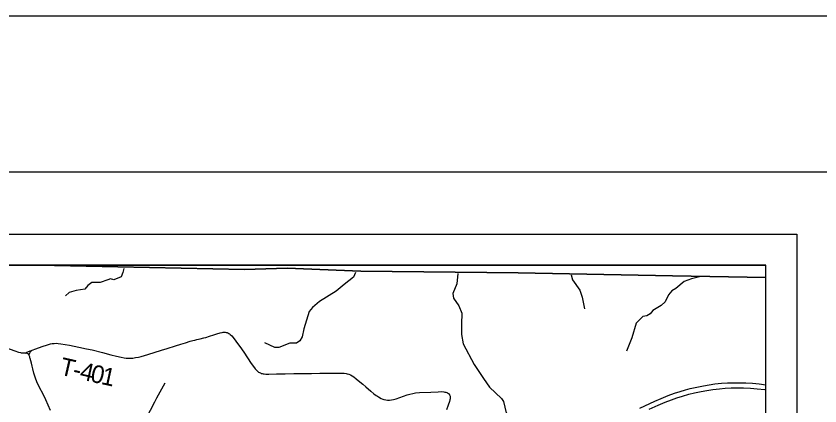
# Model space of a CAD drawing. Extents: x 0 to 34, y 0 to 22.
# Drawn here: x 6.991 to 9.575, y 20.748 to 22 of the extents above; entities that cross this region are included whole.
import ezdxf

# ---------------------------------------------------------------- set-up
doc = ezdxf.new("R2010")
doc.units = 0
for name, color, linetype in [('GM_X_Adjacent_County', 7, 'Continuous'), ('GM_X_County', 7, 'Continuous'), ('GM_X_Minor_River', 7, 'Continuous'), ('GM_X_State_Route', 7, 'Continuous'), ('GM_X_Township', 7, 'Continuous'), ('GM_X_Township_Road', 7, 'Continuous'), ('GM_X_Township_Road_Text', 7, 'Continuous'), ('SH_Border', 7, 'Continuous'), ('SH_Cut_Line', 7, 'Continuous'), ('SH_Data', 7, 'Continuous')]:
    doc.layers.add(name, color=color, linetype=linetype)

msp = doc.modelspace()

# ---------------------------------------------------------------- linework, layer by layer
at = {"layer": 'GM_X_Adjacent_County'}
for points in [[(9.4013, 21.1598), (9.4013, 21.2003), (7.0736, 21.2003)], [(7.0736, 21.2003), (7.1148, 21.1984), (7.7257, 21.186), (7.8629, 21.1903), (8.099, 21.1805), (8.605, 21.1754), (9.1005, 21.1651), (9.4013, 21.1598)]]:
    msp.add_lwpolyline(points, dxfattribs=at)
at = {"layer": 'GM_X_County'}
for points in [[(7.0736, 21.2003), (2.6013, 21.2003), (2.6013, 14.4003), (9.4013, 14.4003), (9.4013, 21.1598)], [(9.4013, 21.1598), (9.1005, 21.1651), (8.605, 21.1754), (8.099, 21.1805), (7.8629, 21.1903), (7.7257, 21.186), (7.1148, 21.1984), (7.0736, 21.2003)]]:
    msp.add_lwpolyline(points, dxfattribs=at)
at = {"layer": 'GM_X_Minor_River'}
for points in [[(7.3376, 21.1892), (7.3341, 21.1764), (7.3289, 21.1626), (7.3055, 21.1523), (7.2944, 21.1563), (7.2866, 21.1522), (7.2612, 21.1442), (7.2347, 21.1445), (7.2215, 21.1346), (7.2129, 21.1228), (7.1845, 21.1181), (7.1622, 21.1124), (7.1498, 21.1017)], [(8.0827, 21.1766), (8.0762, 21.1611), (8.0456, 21.1375), (8.0203, 21.1166), (7.9663, 21.083), (7.9444, 21.0639), (7.9331, 21.0514), (7.9167, 20.9952), (7.9108, 20.9694), (7.9036, 20.9572), (7.8927, 20.9496), (7.8715, 20.9495), (7.836, 20.9353), (7.8231, 20.9357), (7.7913, 20.9507)], [(8.4113, 21.1729), (8.4074, 21.1403), (8.3955, 21.1084), (8.397, 21.0936), (8.4138, 21.0694), (8.4237, 21.046), (8.4228, 21.0099), (8.4233, 20.9773), (8.4287, 20.9473), (8.4631, 20.8811), (8.4939, 20.8353), (8.5133, 20.8077), (8.5517, 20.7718), (8.5578, 20.7616), (8.5663, 20.7255), (8.5842, 20.6949), (8.5964, 20.6828)], [(8.7758, 21.169), (8.7791, 21.1532), (8.8035, 21.1198), (8.8111, 21.0967), (8.8181, 21.0599)], [(9.1924, 21.163), (9.1618, 21.1563), (9.1384, 21.1471), (9.112, 21.125), (9.0984, 21.1178), (9.0882, 21.1045), (9.0773, 21.0824), (9.0641, 21.0702), (9.0381, 21.0538), (9.0294, 21.0439), (9.0185, 21.0375), (9.006, 21.0348), (8.9837, 21.0131), (8.9707, 20.9667), (8.9527, 20.9234)], [(7.41, 20.7073), (7.4374, 20.7605), (7.4442, 20.7738), (7.4708, 20.8217)]]:
    msp.add_lwpolyline(points, dxfattribs=at)
at = {"layer": 'GM_X_State_Route'}
for points in [[(8.9964, 20.7408), (9.0442, 20.7633), (9.064, 20.772), (9.0871, 20.7811), (9.1075, 20.7886), (9.1252, 20.7943), (9.143, 20.7995), (9.158, 20.8034), (9.1792, 20.8083), (9.2004, 20.8127), (9.2188, 20.8157), (9.2372, 20.8182), (9.2588, 20.8203), (9.2774, 20.8216), (9.296, 20.8222), (9.3146, 20.8223), (9.3363, 20.8217), (9.3579, 20.8204), (9.3795, 20.8184), (9.4013, 20.8158)], [(9.0263, 20.7369), (9.0545, 20.7498), (9.0774, 20.7596), (9.0976, 20.7676), (9.1152, 20.7739), (9.133, 20.7795), (9.1539, 20.7854), (9.172, 20.7899), (9.1933, 20.7944), (9.2117, 20.7977), (9.2302, 20.8003), (9.2518, 20.8028), (9.2704, 20.8043), (9.289, 20.8053), (9.3077, 20.8057), (9.3294, 20.8054), (9.3512, 20.8044), (9.3728, 20.8026), (9.3976, 20.8), (9.4013, 20.7995)]]:
    msp.add_lwpolyline(points, dxfattribs=at)
at = {"layer": 'GM_X_Township'}
for p, q in [((7.0736, 21.2003), (6.2234, 21.2003)), ((9.4013, 16.1226), (9.4013, 21.1598))]:
    msp.add_line(p, q, dxfattribs=at)
msp.add_lwpolyline([(9.4013, 21.1598), (9.1005, 21.1651), (8.605, 21.1754), (8.099, 21.1805), (7.8629, 21.1903), (7.7257, 21.186), (7.1148, 21.1984), (7.0736, 21.2003)], dxfattribs=at)
at = {"layer": 'GM_X_Township_Road'}
for points in [[(7.021, 20.9175), (7.0206, 20.9175), (7.0123, 20.917), (7.0092, 20.9172), (7.0062, 20.9178), (7.0002, 20.9194), (6.9885, 20.9235), (6.9359, 20.9421), (6.9241, 20.946), (6.9065, 20.9521), (6.8862, 20.9599), (6.8661, 20.9679), (6.8459, 20.976), (6.8371, 20.979), (6.8311, 20.9806), (6.8281, 20.9811), (6.8219, 20.9815), (6.8188, 20.9815), (6.8126, 20.9808), (6.8065, 20.9797), (6.7974, 20.9777), (6.7734, 20.9715), (6.683, 20.95)], [(7.0415, 20.9257), (7.0431, 20.9264), (7.0545, 20.9312), (7.0751, 20.9383), (7.0928, 20.9441), (7.1018, 20.9466), (7.1079, 20.9478), (7.114, 20.9486), (7.1202, 20.9488), (7.1264, 20.9486), (7.1357, 20.9474), (7.1631, 20.9423), (7.1936, 20.9362), (7.2179, 20.9314), (7.2361, 20.9273), (7.2692, 20.9192), (7.2963, 20.912), (7.3143, 20.9073), (7.3294, 20.9038), (7.3385, 20.9022), (7.3447, 20.9014), (7.3509, 20.9009), (7.3571, 20.9009), (7.3664, 20.9015), (7.3756, 20.9028), (7.3847, 20.9046), (7.3937, 20.9069), (7.4145, 20.9132), (7.459, 20.9268), (7.4768, 20.9323), (7.5036, 20.9403), (7.5213, 20.9459), (7.5361, 20.9506), (7.5509, 20.9554), (7.5598, 20.9579), (7.5658, 20.9594), (7.5718, 20.9608), (7.5835, 20.9634), (7.595, 20.9663), (7.6009, 20.9679), (7.6126, 20.9717), (7.6274, 20.9763), (7.6362, 20.979), (7.6477, 20.9824), (7.6538, 20.9837), (7.6574, 20.9842), (7.6601, 20.9844), (7.6634, 20.9843), (7.6664, 20.984), (7.6694, 20.9831), (7.6722, 20.982), (7.675, 20.9807), (7.6775, 20.979), (7.6799, 20.9771), (7.6843, 20.9727), (7.6922, 20.9632), (7.6979, 20.9559), (7.7035, 20.9485), (7.7108, 20.9384), (7.7229, 20.9204), (7.7349, 20.9023), (7.7469, 20.8843), (7.7541, 20.8742), (7.7598, 20.8668), (7.7639, 20.8622), (7.7661, 20.8601), (7.7685, 20.8582), (7.7709, 20.8564), (7.7736, 20.8548), (7.7764, 20.8534), (7.7792, 20.8523), (7.7822, 20.8514), (7.7852, 20.8508), (7.7883, 20.8504), (7.7945, 20.8501), (7.8038, 20.85), (7.8286, 20.8504), (7.8565, 20.851), (7.8845, 20.8513), (7.9062, 20.8516), (7.9248, 20.8519), (7.9403, 20.8521), (7.9681, 20.8525), (7.9836, 20.8525), (8.0053, 20.8526), (8.0395, 20.8527), (8.0457, 20.8524), (8.0519, 20.8516), (8.0549, 20.8511), (8.0609, 20.8494), (8.0666, 20.847), (8.072, 20.8441), (8.0772, 20.8407), (8.0845, 20.8351), (8.0964, 20.8253), (8.1057, 20.8171), (8.115, 20.8089), (8.1315, 20.7947), (8.1412, 20.787), (8.1487, 20.7815), (8.1531, 20.7787)], [(7.021, 20.9175), (7.0228, 20.9187), (7.0245, 20.9195), (7.0259, 20.9201), (7.0341, 20.9235), (7.0365, 20.9242), (7.039, 20.9249), (7.0415, 20.9257)], [(7.0334, 20.9108), (7.0337, 20.913), (7.0339, 20.9144), (7.0342, 20.9155), (7.0354, 20.9184), (7.0365, 20.9201), (7.0383, 20.9226), (7.0395, 20.9239), (7.0403, 20.9246), (7.0415, 20.9257)], [(7.0334, 20.9108), (7.0327, 20.9119), (7.0315, 20.9134), (7.0303, 20.9145), (7.0288, 20.9155), (7.0275, 20.9163), (7.0255, 20.917), (7.0235, 20.9175), (7.021, 20.9175)], [(7.1018, 20.7331), (7.0943, 20.7501), (7.0869, 20.7672), (7.0803, 20.7812), (7.0647, 20.8114), (7.0586, 20.825), (7.0536, 20.8371), (7.0518, 20.8428), (7.0486, 20.8525), (7.0453, 20.8665), (7.0431, 20.8755), (7.041, 20.8845), (7.037, 20.8995), (7.0361, 20.9026), (7.0354, 20.9051), (7.0348, 20.9072), (7.0339, 20.9097), (7.0334, 20.9108)], [(8.1531, 20.7787), (8.1565, 20.7765), (8.1647, 20.7719), (8.1704, 20.7695), (8.1733, 20.7685), (8.1793, 20.7671), (8.1855, 20.7664), (8.1917, 20.7663), (8.1979, 20.7669), (8.204, 20.7679), (8.213, 20.7703), (8.2248, 20.7742), (8.2481, 20.7829), (8.257, 20.7857), (8.266, 20.7879), (8.2752, 20.7894), (8.2876, 20.7904), (8.3248, 20.792), (8.3478, 20.793), (8.3576, 20.7935), (8.3658, 20.7929), (8.3697, 20.7923), (8.3727, 20.7916), (8.3755, 20.7905), (8.3782, 20.7895), (8.3806, 20.7879), (8.3828, 20.786), (8.3845, 20.7837), (8.3858, 20.7809), (8.3863, 20.7791), (8.3865, 20.7772), (8.3867, 20.7736), (8.3864, 20.7707), (8.3855, 20.7669), (8.384, 20.7614), (8.38, 20.7496), (8.3749, 20.7349)]]:
    msp.add_lwpolyline(points, dxfattribs=at)
at = {"layer": 'SH_Border'}
msp.add_lwpolyline([(2, 21.5), (33.5, 21.5), (33.5, 0.5), (2, 0.5)], close=True, dxfattribs=at)
at = {"layer": 'SH_Cut_Line'}
msp.add_lwpolyline([(0, 0), (34, 0), (34, 22), (0, 22)], close=True, dxfattribs=at)
at = {"layer": 'SH_Data'}
for p, q in [((2.5, 21.2997), (9.5, 21.2997)), ((9.5, 21.2997), (9.5, 14.2997)), ((2.6, 21.1997), (9.4, 21.1997)), ((9.4, 21.1997), (9.4, 14.3997))]:
    msp.add_line(p, q, dxfattribs=at)

# ---------------------------------------------------------------- texts
at = {"layer": 'GM_X_Township_Road_Text'}
for s, rotation, p in [('T', 347.0719, (7.1289, 20.8489)), ('4', 347.1127, (7.1931, 20.8342)), ('0', 347.2214, (7.2273, 20.8263)), ('-', 347.0752, (7.1703, 20.8394)), ('1', 347.5961, (7.2619, 20.8185))]:
    msp.add_text(s, height=0.0568, rotation=rotation, dxfattribs=at).set_placement(p)

doc.saveas('drawing.dxf')
